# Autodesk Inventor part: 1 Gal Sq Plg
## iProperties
Author: ARennick
Shininess: 64.0
Angle Display Precision: 2
Document Length Units: 11272
Document Angle Units: 11286
Document Time Units: 11279
Document Mass Units: 11290
Document Length Units Precision: 3
Document Angle Units Precision: 2
Compacted: True
PropertySet Name: _Private Model Information
Created: 2002-01
Part Number: 1 Gal Sq Plg
Material: Steel, Mild
Description: 1 Square Plug, 150psi Galv
Document SubType Name: Modeling
Designer: ARennick
Control State: 0
Master: False
Checked Out: False
PropertySet Name: Design Tracking Control
Density: 0.0
Volumn: 0.0
Area: 0.0
PropertySet Name: Model Information
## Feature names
1. Threaded [Extrusion]
2. Square Ext [Extrusion]
3. Square Chamf [Chamfer]
4. Fillet1
5. Hex Ext [Extrusion]
6. Revolution2
